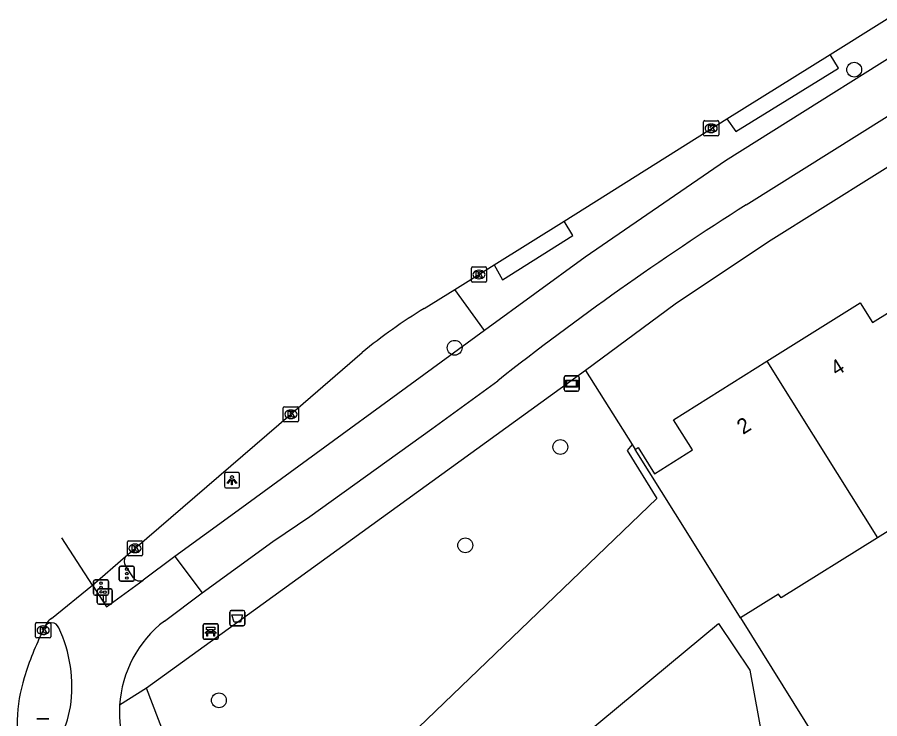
# Model space of a CAD drawing. Extents: x 160077 to 160945, y 386481 to 387498.
# Drawn here: x 160092.9 to 160149.7, y 387323.5 to 387369.8 of the extents above; entities that cross this region are included whole.
import ezdxf

# ---------------------------------------------------------------- set-up
doc = ezdxf.new("R2010")
doc.units = 0
for name, color, linetype in [('IMGEO_Afvalbak', 7, 'Continuous'), ('IMGEO_Bank', 7, 'Continuous'), ('IMGEO_Berm_open', 7, 'Continuous'), ('IMGEO_Boom', 7, 'Continuous'), ('IMGEO_Drukknoppaal', 7, 'Continuous'), ('IMGEO_Fietspad_gesloten', 7, 'Continuous'), ('IMGEO_Fietspad_open', 7, 'Continuous'), ('IMGEO_Groenvoorziening', 7, 'Continuous'), ('IMGEO_Kolk', 7, 'Continuous'), ('IMGEO_Lichtpunt', 7, 'Continuous'), ('IMGEO_Pand', 7, 'Continuous'), ('IMGEO_Pand_nummerreeks', 7, 'Continuous'), ('IMGEO_Portaal', 7, 'Continuous'), ('IMGEO_Rijbaan_lokaal_gesloten', 7, 'Continuous'), ('IMGEO_Rijbaan_regionaal_gesloten', 7, 'Continuous'), ('IMGEO_Verkeersregelinstallatiepaal', 7, 'Continuous'), ('IMGEO_Verklikker', 7, 'Continuous'), ('IMGEO_Voetpad_open', 7, 'Continuous')]:
    doc.layers.add(name, color=color, linetype=linetype)

msp = doc.modelspace()

# ---------------------------------------------------------------- linework, layer by layer
at = {"layer": 'IMGEO_Afvalbak'}
for p, q in [((160106.866, 387329.778), (160106.866, 387330.578)), ((160106.866, 387330.578), (160106.866, 387329.778)), ((160106.966, 387330.678), (160107.756, 387330.678)), ((160107.756, 387330.678), (160106.966, 387330.678)), ((160107.856, 387330.578), (160107.856, 387329.778)), ((160107.856, 387329.778), (160107.856, 387330.578)), ((160107.756, 387329.678), (160106.966, 387329.678)), ((160106.966, 387329.678), (160107.756, 387329.678))]:
    msp.add_line(p, q, dxfattribs=at)
msp.add_lwpolyline([(160107.009, 387330.392), (160107.713, 387330.392), (160107.564, 387329.922), (160107.158, 387329.922), (160107.009, 387330.392)], dxfattribs=at)
for centre, start, end in [((160106.966, 387330.578), 90, 180), ((160106.966, 387330.578), 90, 180), ((160107.756, 387330.578), 0, 90), ((160107.756, 387330.578), 360, 90), ((160106.966, 387329.778), 180, 270), ((160106.966, 387329.778), 180, 270), ((160107.756, 387329.778), 270, 0), ((160107.756, 387329.778), 270, 0)]:
    msp.add_arc(centre, 0.1, start, end, dxfattribs=at)
at = {"layer": 'IMGEO_Bank'}
for p, q in [((160105.112, 387328.873), (160105.112, 387329.714)), ((160105.112, 387329.714), (160105.112, 387328.873)), ((160105.187, 387329.798), (160106.028, 387329.798)), ((160106.028, 387329.798), (160105.187, 387329.798)), ((160105.421, 387329.304), (160105.421, 387329.41)), ((160105.465, 387329.41), (160105.465, 387329.304)), ((160105.753, 387329.416), (160105.471, 387329.416)), ((160105.759, 387329.304), (160105.759, 387329.41)), ((160105.803, 387329.41), (160105.803, 387329.304)), ((160106.112, 387329.723), (160106.112, 387328.882)), ((160106.112, 387328.882), (160106.112, 387329.723)), ((160106.037, 387328.798), (160105.196, 387328.798)), ((160105.196, 387328.798), (160106.037, 387328.798)), ((160105.809, 387329.196), (160105.416, 387329.196)), ((160105.471, 387329.298), (160105.753, 387329.298))]:
    msp.add_line(p, q, dxfattribs=at)
for points in [[(160105.415, 387329.416), (160105.329, 387329.416), (160105.329, 387329.577), (160105.892, 387329.577), (160105.892, 387329.416), (160105.809, 387329.416)], [(160105.359, 387329.196), (160105.217, 387329.196), (160105.329, 387329.298), (160105.415, 387329.298)], [(160105.409, 387329.189), (160105.409, 387328.982), (160105.366, 387328.982), (160105.366, 387329.189)], [(160105.809, 387329.298), (160105.892, 387329.298), (160106.004, 387329.196), (160105.865, 387329.196)], [(160105.859, 387329.189), (160105.859, 387328.982), (160105.815, 387328.982), (160105.815, 387329.189)]]:
    msp.add_lwpolyline(points, dxfattribs=at)
for centre, radius, start, end in [((160105.19, 387329.72), 0.0779, 92.4484, 184.2845), ((160105.19, 387329.72), 0.0779, 92.4484, 184.2845), ((160105.414, 387329.409), 0.00671, 2.8957, 87.1043), ((160105.471, 387329.409), 0.00671, 92.8957, 177.1043), ((160105.753, 387329.409), 0.00671, 2.8957, 87.1043), ((160105.81, 387329.409), 0.00671, 92.8957, 177.1043), ((160106.034, 387329.72), 0.0779, 2.4484, 94.2845), ((160106.034, 387329.72), 0.0779, 2.4484, 94.2845), ((160105.19, 387328.876), 0.0779, 182.4484, 274.2845), ((160105.19, 387328.876), 0.0779, 182.4484, 274.2845), ((160105.359, 387329.189), 0.00671, 2.8957, 87.1043), ((160105.416, 387329.189), 0.00671, 92.8957, 177.1043), ((160105.414, 387329.305), 0.00671, 272.8957, 357.1043), ((160105.471, 387329.305), 0.00671, 182.8957, 267.1043), ((160105.753, 387329.305), 0.00671, 272.8957, 357.1043), ((160105.81, 387329.305), 0.00671, 182.8957, 267.1043), ((160105.808, 387329.189), 0.00671, 2.8957, 87.1043), ((160105.865, 387329.189), 0.00671, 92.8957, 177.1043), ((160106.034, 387328.876), 0.0779, 272.4484, 4.2845), ((160106.034, 387328.876), 0.0779, 272.4484, 4.2845)]:
    msp.add_arc(centre, radius, start, end, dxfattribs=at)
at = {"layer": 'IMGEO_Berm_open'}
msp.add_lwpolyline([(160123.646, 387349.147), (160121.686, 387351.844)], dxfattribs=at)
at = {"layer": 'IMGEO_Boom'}
for centre in [(160147.993, 387366.324), (160121.676, 387347.998), (160128.638, 387341.455), (160122.377, 387334.973), (160106.151, 387324.76)]:
    msp.add_circle(centre, 0.489, dxfattribs=at)
at = {"layer": 'IMGEO_Drukknoppaal'}
for p, q in [((160098.14, 387331.199), (160098.14, 387331.999)), ((160098.14, 387331.999), (160098.14, 387331.199)), ((160098.24, 387332.099), (160099.03, 387332.099)), ((160099.03, 387332.099), (160098.24, 387332.099)), ((160099.13, 387331.999), (160099.13, 387331.199)), ((160099.13, 387331.199), (160099.13, 387331.999)), ((160099.03, 387331.099), (160098.24, 387331.099)), ((160098.24, 387331.099), (160099.03, 387331.099))]:
    msp.add_line(p, q, dxfattribs=at)
msp.add_lwpolyline([(160098.71, 387331.724), (160098.71, 387331.224), (160098.56, 387331.224), (160098.56, 387331.724), (160098.71, 387331.724)], dxfattribs=at)
msp.add_circle((160098.635, 387331.889), 0.085, dxfattribs=at)
for centre, start, end in [((160098.24, 387331.999), 90, 180), ((160098.24, 387331.999), 90, 180), ((160099.03, 387331.999), 0, 90), ((160099.03, 387331.999), 360, 90), ((160098.24, 387331.199), 180, 270), ((160098.24, 387331.199), 180, 270), ((160099.03, 387331.199), 270, 0), ((160099.03, 387331.199), 270, 0)]:
    msp.add_arc(centre, 0.1, start, end, dxfattribs=at)
at = {"layer": 'IMGEO_Fietspad_gesloten'}
for points in [[(160103.253, 387334.242), (160101.156, 387332.685)], [(160103.253, 387334.242), (160105.052, 387331.844)], [(160097.829, 387332.341), (160098.74, 387330.916), (160101.156, 387332.685)], [(160102.559, 387329.987), (160105.052, 387331.844)]]:
    msp.add_lwpolyline(points, dxfattribs=at)
for centre, radius, start, end in [((160107.238, 387323.948), 7.64, 127.7667, 176.3126), ((160095.132, 387329.363), 0.507, 21.0736, 154.875), ((160087.228, 387325.646), 9.241, 351.7874, 24.9551), ((160089.532, 387325.502), 6.943, 312.0535, 350.2464), ((160107.216, 387323.943), 7.619, 176.2636, 198.7472)]:
    msp.add_arc(centre, radius, start, end, dxfattribs=at)
at = {"layer": 'IMGEO_Fietspad_open'}
for points in [[(160140.876, 387357.421), (160187.132, 387386.441), (160191.413, 387389.134), (160255.073, 387429.003), (160256.289, 387429.772), (160273.122, 387440.293), (160278.495, 387443.763), (160282.321, 387446.132), (160288.169, 387449.309)], [(160277.663, 387446.976), (160201.088, 387399.003), (160139.521, 387360.312), (160130.284, 387353.98), (160123.646, 387349.147)], [(160123.646, 387349.147), (160107.41, 387337.279), (160103.253, 387334.242)], [(160105.052, 387331.844), (160109.714, 387335.223), (160112.133, 387336.88), (160120.167, 387342.659), (160124.516, 387345.828)]]:
    msp.add_lwpolyline(points, dxfattribs=at)
msp.add_arc((160249.179, 387187.245), 201.716, 122.47325, 128.17094, dxfattribs=at)
at = {"layer": 'IMGEO_Groenvoorziening'}
for points in [[(160130.296, 387346.507), (160133.36, 387341.629)], [(160133.36, 387341.629), (160133.048, 387341.231), (160135, 387338.07), (160115.943, 387319.74), (160120.193, 387314.153), (160139.057, 387329.83), (160141.124, 387326.758), (160144.653, 387307.431), (160149.674, 387308.189)], [(160133.36, 387341.629), (160133.57, 387341.295)], [(160140.514, 387330.194), (160147.536, 387318.896)]]:
    msp.add_lwpolyline(points, dxfattribs=at)
at = {"layer": 'IMGEO_Kolk'}
for p, q in [((160138.073, 387362.04), (160138.073, 387362.892)), ((160138.148, 387362.966), (160139, 387362.966)), ((160139.074, 387362.892), (160139.074, 387362.04)), ((160138.561, 387362.746), (160138.586, 387362.746)), ((160139, 387361.966), (160138.148, 387361.966)), ((160138.584, 387362.186), (160138.559, 387362.186)), ((160122.779, 387352.398), (160122.779, 387353.25)), ((160122.854, 387353.324), (160123.706, 387353.324)), ((160123.78, 387353.25), (160123.78, 387352.398)), ((160123.267, 387353.104), (160123.292, 387353.104)), ((160123.706, 387352.324), (160122.854, 387352.324)), ((160123.29, 387352.544), (160123.265, 387352.544)), ((160110.469, 387344.113), (160111.321, 387344.113)), ((160110.394, 387343.187), (160110.394, 387344.039)), ((160110.882, 387343.893), (160110.907, 387343.893)), ((160111.395, 387344.039), (160111.395, 387343.187)), ((160111.321, 387343.113), (160110.469, 387343.113)), ((160110.905, 387343.333), (160110.88, 387343.333)), ((160100.124, 387334.349), (160100.124, 387335.201)), ((160100.199, 387335.275), (160101.051, 387335.275)), ((160100.612, 387335.055), (160100.637, 387335.055)), ((160101.125, 387335.201), (160101.125, 387334.349)), ((160100.635, 387334.495), (160100.61, 387334.495)), ((160101.051, 387334.275), (160100.199, 387334.275)), ((160094.077, 387328.954), (160094.077, 387329.806)), ((160094.152, 387329.88), (160095.004, 387329.88)), ((160094.565, 387329.66), (160094.59, 387329.66)), ((160095.078, 387329.806), (160095.078, 387328.954)), ((160095.004, 387328.88), (160094.152, 387328.88)), ((160094.588, 387329.1), (160094.563, 387329.1))]:
    msp.add_line(p, q, dxfattribs=at)
for points in [[(160138.073, 387362.04), (160138.073, 387362.892)], [(160138.148, 387362.966), (160139, 387362.966)], [(160139.074, 387362.892), (160139.074, 387362.04)], [(160138.394, 387362.666), (160138.517, 387362.666), (160138.517, 387362.515), (160138.647, 387362.666), (160138.811, 387362.666), (160138.665, 387362.515), (160138.818, 387362.266), (160138.666, 387362.266), (160138.581, 387362.43), (160138.517, 387362.363), (160138.517, 387362.266), (160138.394, 387362.266), (160138.394, 387362.666)], [(160139, 387361.966), (160138.148, 387361.966)], [(160122.779, 387352.398), (160122.779, 387353.25)], [(160122.854, 387353.324), (160123.706, 387353.324)], [(160123.78, 387353.25), (160123.78, 387352.398)], [(160123.1, 387353.024), (160123.223, 387353.024), (160123.223, 387352.873), (160123.353, 387353.024), (160123.517, 387353.024), (160123.371, 387352.873), (160123.524, 387352.624), (160123.372, 387352.624), (160123.287, 387352.788), (160123.223, 387352.721), (160123.223, 387352.624), (160123.1, 387352.624), (160123.1, 387353.024)], [(160123.706, 387352.324), (160122.854, 387352.324)], [(160110.469, 387344.113), (160111.321, 387344.113)], [(160110.394, 387343.187), (160110.394, 387344.039)], [(160110.715, 387343.813), (160110.838, 387343.813), (160110.838, 387343.662), (160110.968, 387343.813), (160111.132, 387343.813), (160110.986, 387343.662), (160111.139, 387343.413), (160110.987, 387343.413), (160110.902, 387343.577), (160110.838, 387343.51), (160110.838, 387343.413), (160110.715, 387343.413), (160110.715, 387343.813)], [(160111.395, 387344.039), (160111.395, 387343.187)], [(160111.321, 387343.113), (160110.469, 387343.113)], [(160100.124, 387334.349), (160100.124, 387335.201)], [(160100.199, 387335.275), (160101.051, 387335.275)], [(160101.125, 387335.201), (160101.125, 387334.349)], [(160100.445, 387334.975), (160100.568, 387334.975), (160100.568, 387334.824), (160100.698, 387334.975), (160100.862, 387334.975), (160100.716, 387334.824), (160100.869, 387334.575), (160100.717, 387334.575), (160100.632, 387334.739), (160100.568, 387334.672), (160100.568, 387334.575), (160100.445, 387334.575), (160100.445, 387334.975)], [(160101.051, 387334.275), (160100.199, 387334.275)], [(160094.077, 387328.954), (160094.077, 387329.806)], [(160094.152, 387329.88), (160095.004, 387329.88)], [(160094.398, 387329.58), (160094.521, 387329.58), (160094.521, 387329.429), (160094.651, 387329.58), (160094.815, 387329.58), (160094.669, 387329.429), (160094.822, 387329.18), (160094.67, 387329.18), (160094.585, 387329.344), (160094.521, 387329.277), (160094.521, 387329.18), (160094.398, 387329.18), (160094.398, 387329.58)], [(160095.078, 387329.806), (160095.078, 387328.954)], [(160095.004, 387328.88), (160094.152, 387328.88)]]:
    msp.add_lwpolyline(points, dxfattribs=at)
for centre, start, end in [((160138.15, 387362.89), 91.552, 178.448), ((160138.15, 387362.89), 91.552, 178.448), ((160138.998, 387362.89), 1.552, 88.448), ((160138.998, 387362.89), 1.552, 88.448), ((160138.15, 387362.042), 181.552, 268.448), ((160138.15, 387362.042), 181.552, 268.448), ((160138.998, 387362.042), 271.552, 358.448), ((160138.998, 387362.042), 271.552, 358.448), ((160122.856, 387353.248), 91.552, 178.448), ((160122.856, 387353.248), 91.552, 178.448), ((160123.704, 387353.248), 1.552, 88.448), ((160123.704, 387353.248), 1.552, 88.448), ((160122.856, 387352.4), 181.552, 268.448), ((160122.856, 387352.4), 181.552, 268.448), ((160123.704, 387352.4), 271.552, 358.448), ((160123.704, 387352.4), 271.552, 358.448), ((160110.471, 387344.037), 91.552, 178.448), ((160110.471, 387344.037), 91.552, 178.448), ((160111.319, 387344.037), 1.552, 88.448), ((160111.319, 387344.037), 1.552, 88.448), ((160110.471, 387343.189), 181.552, 268.448), ((160110.471, 387343.189), 181.552, 268.448), ((160111.319, 387343.189), 271.552, 358.448), ((160111.319, 387343.189), 271.552, 358.448), ((160100.201, 387335.199), 91.552, 178.448), ((160100.201, 387335.199), 91.552, 178.448), ((160101.049, 387335.199), 1.552, 88.448), ((160101.049, 387335.199), 1.552, 88.448), ((160100.201, 387334.351), 181.552, 268.448), ((160100.201, 387334.351), 181.552, 268.448), ((160101.049, 387334.351), 271.552, 358.448), ((160101.049, 387334.351), 271.552, 358.448), ((160094.154, 387329.804), 91.552, 178.448), ((160094.154, 387329.804), 91.552, 178.448), ((160095.002, 387329.804), 1.552, 88.448), ((160095.002, 387329.804), 1.552, 88.448), ((160094.154, 387328.956), 181.552, 268.448), ((160094.154, 387328.956), 181.552, 268.448), ((160095.002, 387328.956), 271.552, 358.448), ((160095.002, 387328.956), 271.552, 358.448)]:
    msp.add_arc(centre, 0.0765, start, end, dxfattribs=at)
for centre, major_axis, ratio, start_param, end_param in [((160138.56, 387362.466), (-0.387, 0.002), 0.722429, 4.712389, 7.853982), ((160138.585, 387362.466), (-0.39, 0.002), 0.717154, 1.570796, 4.712389), ((160123.266, 387352.824), (-0.387, 0.002), 0.722429, 4.712389, 7.853982), ((160123.291, 387352.824), (-0.39, 0.002), 0.717154, 1.570796, 4.712389), ((160110.881, 387343.613), (-0.387, 0.002), 0.722429, 4.712389, 7.853982), ((160110.906, 387343.613), (-0.39, 0.002), 0.717154, 1.570796, 4.712389), ((160100.611, 387334.775), (-0.387, 0.002), 0.722429, 4.712389, 7.853982), ((160100.636, 387334.775), (-0.39, 0.002), 0.717154, 1.570796, 4.712389), ((160094.564, 387329.38), (-0.387, 0.002), 0.722429, 4.712389, 7.853982), ((160094.589, 387329.38), (-0.39, 0.002), 0.717154, 1.570796, 4.712389)]:
    msp.add_ellipse(centre, major_axis=major_axis, ratio=ratio, start_param=start_param, end_param=end_param, dxfattribs=at)
at = {"layer": 'IMGEO_Lichtpunt'}
for p, q in [((160106.513, 387339.673), (160106.513, 387338.866)), ((160106.513, 387339.673), (160106.513, 387338.866)), ((160107.415, 387339.768), (160106.607, 387339.768)), ((160107.415, 387339.768), (160106.607, 387339.768)), ((160107.509, 387338.866), (160107.509, 387339.673)), ((160107.509, 387338.866), (160107.509, 387339.673)), ((160106.607, 387338.772), (160107.415, 387338.772)), ((160106.607, 387338.772), (160107.415, 387338.772))]:
    msp.add_line(p, q, dxfattribs=at)
for points in [[(160106.887, 387339.337), (160106.926, 387339.309), (160106.738, 387339.047), (160106.7, 387339.074), (160106.887, 387339.337)], [(160106.989, 387339.289), (160107.036, 387339.289), (160107.036, 387338.967), (160106.989, 387338.967), (160106.989, 387339.289)], [(160107.099, 387339.309), (160107.137, 387339.336), (160107.324, 387339.074), (160107.285, 387339.046), (160107.099, 387339.309)]]:
    msp.add_lwpolyline(points, dxfattribs=at)
msp.add_circle((160107.012, 387339.471), 0.0994, dxfattribs=at)
for centre, start, end in [((160106.607, 387339.673), 90, 180), ((160106.607, 387339.673), 90, 180), ((160107.415, 387339.673), 0, 90), ((160107.415, 387339.673), 0, 90), ((160106.607, 387338.866), 180, 270), ((160106.607, 387338.866), 180, 270), ((160107.415, 387338.866), 270, 0), ((160107.415, 387338.866), 270, 360)]:
    msp.add_arc(centre, 0.0946, start, end, dxfattribs=at)
at = {"layer": 'IMGEO_Pand'}
for points in [[(160142.245, 387347.104), (160148.398, 387350.953), (160149.203, 387349.666), (160151.693, 387351.223), (160150.274, 387353.491), (160150.392, 387353.565)], [(160133.57, 387341.295), (160133.76, 387341.414), (160134.835, 387339.696), (160137.335, 387341.261), (160136.236, 387343.015), (160136.088, 387343.252), (160142.245, 387347.104)], [(160142.245, 387347.104), (160146.877, 387339.703), (160149.523, 387335.475)], [(160140.514, 387330.194), (160138.029, 387334.168), (160136.222, 387337.057), (160133.57, 387341.295)], [(160158.191, 387340.897), (160149.523, 387335.475)], [(160149.523, 387335.475), (160143.178, 387331.507), (160143.019, 387331.761), (160140.514, 387330.194)]]:
    msp.add_lwpolyline(points, dxfattribs=at)
at = {"layer": 'IMGEO_Portaal'}
for p, q in [((160094.151, 387323.546), (160094.941, 387323.546)), ((160094.941, 387323.546), (160094.151, 387323.546))]:
    msp.add_line(p, q, dxfattribs=at)
at = {"layer": 'IMGEO_Rijbaan_lokaal_gesloten'}
for points in [[(160146.407, 387367.336), (160156.631, 387373.741)], [(160139.613, 387363.077), (160146.407, 387367.336)], [(160128.888, 387356.345), (160139.613, 387363.077)], [(160124.272, 387353.471), (160128.888, 387356.345)], [(160121.686, 387351.844), (160123.28, 387352.824), (160124.272, 387353.471)], [(160119.676, 387350.589), (160121.686, 387351.844)], [(160100.002, 387334.24), (160100.625, 387334.775), (160110.895, 387343.613), (160115.583, 387347.689)], [(160097.829, 387332.341), (160100.002, 387334.24)]]:
    msp.add_lwpolyline(points, dxfattribs=at)
msp.add_arc((160139.122, 387318.805), 37.261, 121.4589, 129.1783, dxfattribs=at)
at = {"layer": 'IMGEO_Rijbaan_regionaal_gesloten'}
for points in [[(160097.829, 387332.341), (160095.802, 387335.473)], [(160095.117, 387330.153), (160097.829, 387332.341)], [(160094.578, 387329.38), (160094.673, 387329.578)]]:
    msp.add_lwpolyline(points, dxfattribs=at)
for centre, radius, start, end in [((160095.772, 387329.188), 1.166, 124.18, 160.4712), ((160111.415, 387320.887), 18.858, 153.2341, 163.479), ((160102.272, 387323.327), 9.402, 161.8852, 196.4532)]:
    msp.add_arc(centre, radius, start, end, dxfattribs=at)
at = {"layer": 'IMGEO_Verkeersregelinstallatiepaal'}
for p, q in [((160099.591, 387332.713), (160099.591, 387333.513)), ((160099.591, 387333.513), (160099.591, 387332.713)), ((160099.691, 387333.613), (160100.481, 387333.613)), ((160100.481, 387333.613), (160099.691, 387333.613)), ((160100.581, 387333.513), (160100.581, 387332.713)), ((160100.581, 387332.713), (160100.581, 387333.513)), ((160097.893, 387331.795), (160097.893, 387332.595)), ((160097.893, 387332.595), (160097.893, 387331.795)), ((160097.993, 387332.695), (160098.783, 387332.695)), ((160098.783, 387332.695), (160097.993, 387332.695)), ((160098.883, 387332.595), (160098.883, 387331.795)), ((160098.883, 387331.795), (160098.883, 387332.595)), ((160100.481, 387332.613), (160099.691, 387332.613)), ((160099.691, 387332.613), (160100.481, 387332.613)), ((160098.783, 387331.695), (160097.993, 387331.695)), ((160097.993, 387331.695), (160098.783, 387331.695))]:
    msp.add_line(p, q, dxfattribs=at)
for centre in [(160100.086, 387333.403), (160100.086, 387333.113), (160100.086, 387332.823), (160098.388, 387332.485), (160098.388, 387332.195), (160098.388, 387331.905)]:
    msp.add_circle(centre, 0.085, dxfattribs=at)
for centre, start, end in [((160099.691, 387333.513), 90, 180), ((160099.691, 387333.513), 90, 180), ((160100.481, 387333.513), 0, 90), ((160100.481, 387333.513), 360, 90), ((160097.993, 387332.595), 90, 180), ((160097.993, 387332.595), 90, 180), ((160098.783, 387332.595), 0, 90), ((160098.783, 387332.595), 360, 90), ((160099.691, 387332.713), 180, 270), ((160099.691, 387332.713), 180, 270), ((160100.481, 387332.713), 270, 0), ((160100.481, 387332.713), 270, 0), ((160097.993, 387331.795), 180, 270), ((160097.993, 387331.795), 180, 270), ((160098.783, 387331.795), 270, 0), ((160098.783, 387331.795), 270, 0)]:
    msp.add_arc(centre, 0.1, start, end, dxfattribs=at)
at = {"layer": 'IMGEO_Verklikker'}
for p, q in [((160128.889, 387345.241), (160128.889, 387346.041)), ((160128.889, 387346.041), (160128.889, 387345.241)), ((160128.989, 387346.141), (160129.779, 387346.141)), ((160129.779, 387346.141), (160128.989, 387346.141)), ((160129.879, 387346.041), (160129.879, 387345.241)), ((160129.879, 387345.241), (160129.879, 387346.041)), ((160129.779, 387345.141), (160128.989, 387345.141)), ((160128.989, 387345.141), (160129.779, 387345.141))]:
    msp.add_line(p, q, dxfattribs=at)
for points in [[(160128.99, 387345.873), (160129.778, 387345.873), (160129.778, 387345.409), (160128.99, 387345.409), (160128.99, 387345.873)], [(160129.055, 387345.808), (160129.055, 387345.474), (160129.713, 387345.474), (160129.713, 387345.808), (160129.055, 387345.808)]]:
    msp.add_lwpolyline(points, dxfattribs=at)
for centre, start, end in [((160128.989, 387346.041), 90, 180), ((160128.989, 387346.041), 90, 180), ((160129.779, 387346.041), 0, 90), ((160129.779, 387346.041), 360, 90), ((160128.989, 387345.241), 180, 270), ((160128.989, 387345.241), 180, 270), ((160129.779, 387345.241), 270, 0), ((160129.779, 387345.241), 270, 0)]:
    msp.add_arc(centre, 0.1, start, end, dxfattribs=at)
at = {"layer": 'IMGEO_Voetpad_open'}
for points in [[(160335.829, 387460.702), (160326.53, 387459.226), (160320.569, 387457.972), (160314.665, 387456.47), (160303.808, 387453.134), (160303.67, 387453.085), (160298.464, 387450.953), (160293.339, 387448.631), (160287.569, 387445.611), (160281.905, 387442.396), (160142.361, 387354.983), (160136.196, 387350.879), (160130.296, 387346.507)], [(160139.613, 387363.077), (160140.191, 387362.257), (160146.959, 387366.435), (160146.407, 387367.336)], [(160124.272, 387353.471), (160124.838, 387352.486), (160129.462, 387355.397), (160128.888, 387356.345)], [(160130.296, 387346.507), (160106.771, 387329.448), (160101.386, 387325.554)], [(160100.52, 387332.831), (160100.021, 387333.604)], [(160101.386, 387325.554), (160099.614, 387324.439)], [(160104.15, 387318.343), (160101.386, 387325.554)]]:
    msp.add_lwpolyline(points, dxfattribs=at)
for centre, radius, start, end in [((160100.414, 387333.934), 0.513, 143.4236, 219.9987), ((160100.926, 387333.14), 0.51, 217.3033, 296.839)]:
    msp.add_arc(centre, radius, start, end, dxfattribs=at)

# ---------------------------------------------------------------- texts
at = {"layer": 'IMGEO_Pand_nummerreeks'}
for s, p in [('4', (160146.828, 387346.101)), ('2', (160140.671, 387342.25))]:
    msp.add_text(s, height=1, rotation=32.0283, dxfattribs=at).set_placement(p)

doc.saveas('drawing.dxf')
